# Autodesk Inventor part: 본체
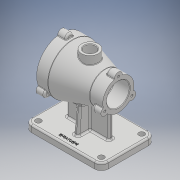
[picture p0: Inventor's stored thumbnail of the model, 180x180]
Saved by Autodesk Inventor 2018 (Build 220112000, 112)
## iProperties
Created: 2020-03
Part Number: 본체
Material: 일반
Document SubType Name: Modeling
Designer: USER
Density: 1 g/cm^3
Appearance: 기본값
Author: USER
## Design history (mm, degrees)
sketch "스케치1"
  geometry: L1 (-67.5, -47.5)-(67.5, -47.5); L2 (67.5, -47.5)-(67.5, 47.5); L3 (67.5, 47.5)-(-67.5, 47.5); L4 (-67.5, 47.5)-(-67.5, -47.5); 3 further points
  constraints: 8 end point, 2 midpoint, 2 parallel, 1 horizontal, 1 horizontal alignment, 1 perpendicular, 1 vertical alignment
  dimensions: "d0" = 135 distance between parallel lines of L4 L2; "d1" = 95 distance between parallel lines of L1 L3; "d93" = 67.5 distance from line of point (0, 47.5) L2 (derived)
extrude "돌출1" new body sketch "스케치1" distance "d2" = 12; taper "d3" = 0 deg
sketch "스케치2"
  geometry: L1 (0, 0)-(0, 87); L2 (50, 87)-(-50, 87); L3 (50, 131)-(30, 131); L4 (-50, 114.5)-(-27, 114.5); L5 (30, 131)-(-27, 114.5); L6 (50, 131)-(50, 87); L7 (50, 87)-(-50, 87); L8 (-50, 114.5)-(-50, 87); 1 further point
  constraints: 16 end point, 3 horizontal, 2 coincident, 2 vertical, 1 collinear, 1 midpoint, 1 perpendicular
  dimensions: "d4" = 87 distance of L1.start L1.end; "d5" = 100 distance of L2.start L2.end; "d6" = 20 distance of L3.start L3.end; "d7" = 88 diameter of L3 L2; "d8" = 23 distance of L4.start L4.end; "d9" = 55 diameter of L4 L2
revolve "회전1" sketch "스케치2" stored, may be unused: angle "d10" = 90 deg
sketch "스케치3"
  geometry: C1 r 44 at (0, 0) reference; C2 r 36 at (0, 0); 1 further point
  constraints: 1 centre point, 1 coincident
  dimensions: "d11" = 72 diameter of C2
extrude "돌출2" cut sketch "스케치3" distance "d12" = 23; taper "d13" = 0 deg
sketch "스케치4"
  geometry: C1 r 36 at (0, 0) reference; C2 r 26 at (0, 0); 1 further point
  constraints: 1 centre point, 1 coincident
  dimensions: "d14" = 52 diameter of C2
extrude "돌출3" cut sketch "스케치4" distance "d15" = 47; taper "d16" = 0 deg
sketch "스케치5"
  geometry: C1 r 26 at (0, 0) reference; C2 r 20 at (0, 0); 1 further point
  constraints: 1 centre point, 1 coincident
  dimensions: "d17" = 40 diameter of C2
extrude "돌출4" cut sketch "스케치5" distance "d18" = 30; taper "d19" = 0 deg
sketch "스케치6"
  geometry: L1 (-37, -4)-(37, -4); L2 (37, -4)-(37, 4); L3 (37, 4)-(-37, 4); L4 (-37, 4)-(-37, -4); 3 further points
  constraints: 8 end point, 2 midpoint, 2 parallel, 1 horizontal, 1 horizontal alignment, 1 perpendicular, 1 vertical alignment
  dimensions: "d21" = 74 distance of L2.end L3.end; "d22" = 8 distance of L1.end L2.end; "d94" = 37 distance from line of point (0, 4) L4 (derived); "d95" = 37 distance from line of L2 point (0, 4) (derived)
extrude "돌출5" join sketch "스케치6" stored distance "d23" = 30; taper "d24" = 0 deg
sketch "스케치7"
  geometry: L1 (0, 0)-(0, 12); L2 (-47.5, 12)-(47.5, 12) reference; L3 (0, 12)-(25, 12); L4 (0, 12)-(-25, 12); L5 (25, 12)-(20.773, 60.318); L6 (-25, 12)-(-20.773, 60.318); L7 (20.773, 60.318)-(-20.773, 60.318)
  constraints: 12 end point, 2 point on line, 1 horizontal, 1 midpoint
  dimensions: "d25" = 25 distance of L1.end L3.end; "d26" = 25 distance of L1.end L4.end; "d27" = 95 deg angle of L2 L5; "d28" = 95 deg angle of L2 L6
extrude "돌출6" join sketch "스케치7" stored distance "d29" = 8; taper "d30" = 0 deg
sketch "스케치8"
  geometry: L1 (0, 0)-(44, 0); C1 r 7 at (44, 0); 1 further point
  constraints: 2 end point, 1 centre point, 1 coincident, 1 horizontal, 1 horizontal alignment, 1 other
  dimensions: "d32" = 14 diameter of C1
extrude "돌출7" join sketch "스케치8" distance "d33" = 15; taper "d34" = 0 deg
sketch "스케치9"
  geometry: A1 r 7 centre (0, 0) between (-0.557, -6.978) and (-0.557, 6.978) reference; 2 further points
  constraints: 1 coincident
hole "구멍1" sketch "스케치9" at (0, 0) diameter "d35" = 4.134; stored, may be unused: countersink angle "d39" = 90 deg, drill point angle "d41" = 118 deg; dims "d36" = 9, "d37" = 4, "d38" = 2, "d40" = 11
sketch "스케치10"
  geometry: L1 (0, 0)-(-27.5, 0); C1 r 20 at (0, 0) reference; C2 r 7 at (-27.5, 0); A1 r 27.5 centre (0, 0) between (27.208, 4) and (27.208, -4) reference; 1 further point
  constraints: 2 end point, 1 centre point, 1 coincident, 1 horizontal, 1 point on circle
  dimensions: "d45" = 14 diameter of C2
extrude "돌출8" join sketch "스케치10" distance "d46" = 15; taper "d47" = 0 deg
sketch "스케치11"
  geometry: A1 r 7 centre (0, 0) between (0.891, 6.943) and (0.891, -6.943) reference; 2 further points
  constraints: 1 coincident
hole "구멍2" sketch "스케치11" at (0, 0) diameter "d48" = 4.134; stored, may be unused: countersink angle "d52" = 90 deg, drill point angle "d54" = 118 deg; dims "d49" = 9, "d50" = 4, "d51" = 2, "d53" = 11
node "작업 평면1"
sketch "스케치12"
  geometry: L1 (-50, 44)-(-50, 6.978) reference; C1 r 15 at (0, 0); 2 further points
  constraints: 1 centre point, 1 coincident
  dimensions: "d59" = 30 diameter of C1; "d60" = 50 distance from line of C1.centre L1
extrude "돌출9" join sketch "스케치12" stored distance "d61" = 15; taper "d62" = 0 deg
sketch "스케치13"
  geometry: C1 r 10 at (0, 0); 1 further point
  constraints: 1 centre point, 1 coincident
  dimensions: "d63" = 20 diameter of C1
extrude "돌출10" cut sketch "스케치13" stored distance "d15" = 47; stored distance "d64" = 15; taper "d65" = 0 deg
chamfer "모따기1" distance "d66" = 1; stored, may be unused: second distance "d67" = 2, angle "d68" = 45 deg
chamfer "모따기2" distance "d69" = 1; stored, may be unused: second distance "d70" = 2, angle "d71" = 45 deg
fillet "모깎기1" dims "d72" = 1
fillet "모깎기2" dims "d73" = 3
fillet "모깎기3" dims "d74" = 3
fillet "모깎기4" dims "d75" = 1
fillet "모깎기5" dims "d76" = 3
fillet "모깎기6" dims "d77" = 3
fillet "모깎기7" dims "d78" = 3
fillet "모깎기8" dims "d79" = 3
fillet "모깎기9" dims "d80" = 3
fillet "모깎기10" dims "d81" = 12
fillet "모깎기11" dims "d82" = 3
sketch "스케치15"
  geometry: C1 r 5 at (-55.5, -35.5); C2 r 5 at (55.5, -35.5); C3 r 5 at (55.5, 35.5); C4 r 5 at (-55.5, 35.5); A1 r 12 centre (-55.5, -35.5) between (-67.5, -35.5) and (-55.5, -47.5) reference; A2 r 12 centre (55.5, -35.5) between (55.5, -47.5) and (67.5, -35.5) reference; A3 r 12 centre (55.5, 35.5) between (67.5, 35.5) and (55.5, 47.5) reference; A4 r 12 centre (-55.5, 35.5) between (-55.5, 47.5) and (-67.5, 35.5) reference; 1 further point
  constraints: 4 centre point, 4 coincident
  dimensions: "d83" = 10 diameter of C1; "d84" = 10 diameter of C2; "d85" = 10 diameter of C3; "d86" = 10 diameter of C4
extrude "돌출11" cut sketch "스케치15" distance "d87" = 15; taper "d88" = 0 deg
sketch "스케치16"
  geometry: L1 (-55.5, -47.5)-(55.5, -47.5) reference; 2 further points
  constraints: 1 vertical alignment, 1 other
  dimensions: "d89" = 10 distance from line of L1 point (0, -37.5)
feature "엠보싱1" sketch "스케치16" dims "d90" = 0.5, "d91" = 0
fillet "모깎기12" dims "d92" = 3
sketch "스케치17"
  geometry: 1 further point
node "솔리드1"
pattern_circular "원형 패턴1" dims angle "d43" = 360 deg
pattern_circular "원형 패턴2" dims angle "d56" = 360 deg
other parameters: "d58" = 132
